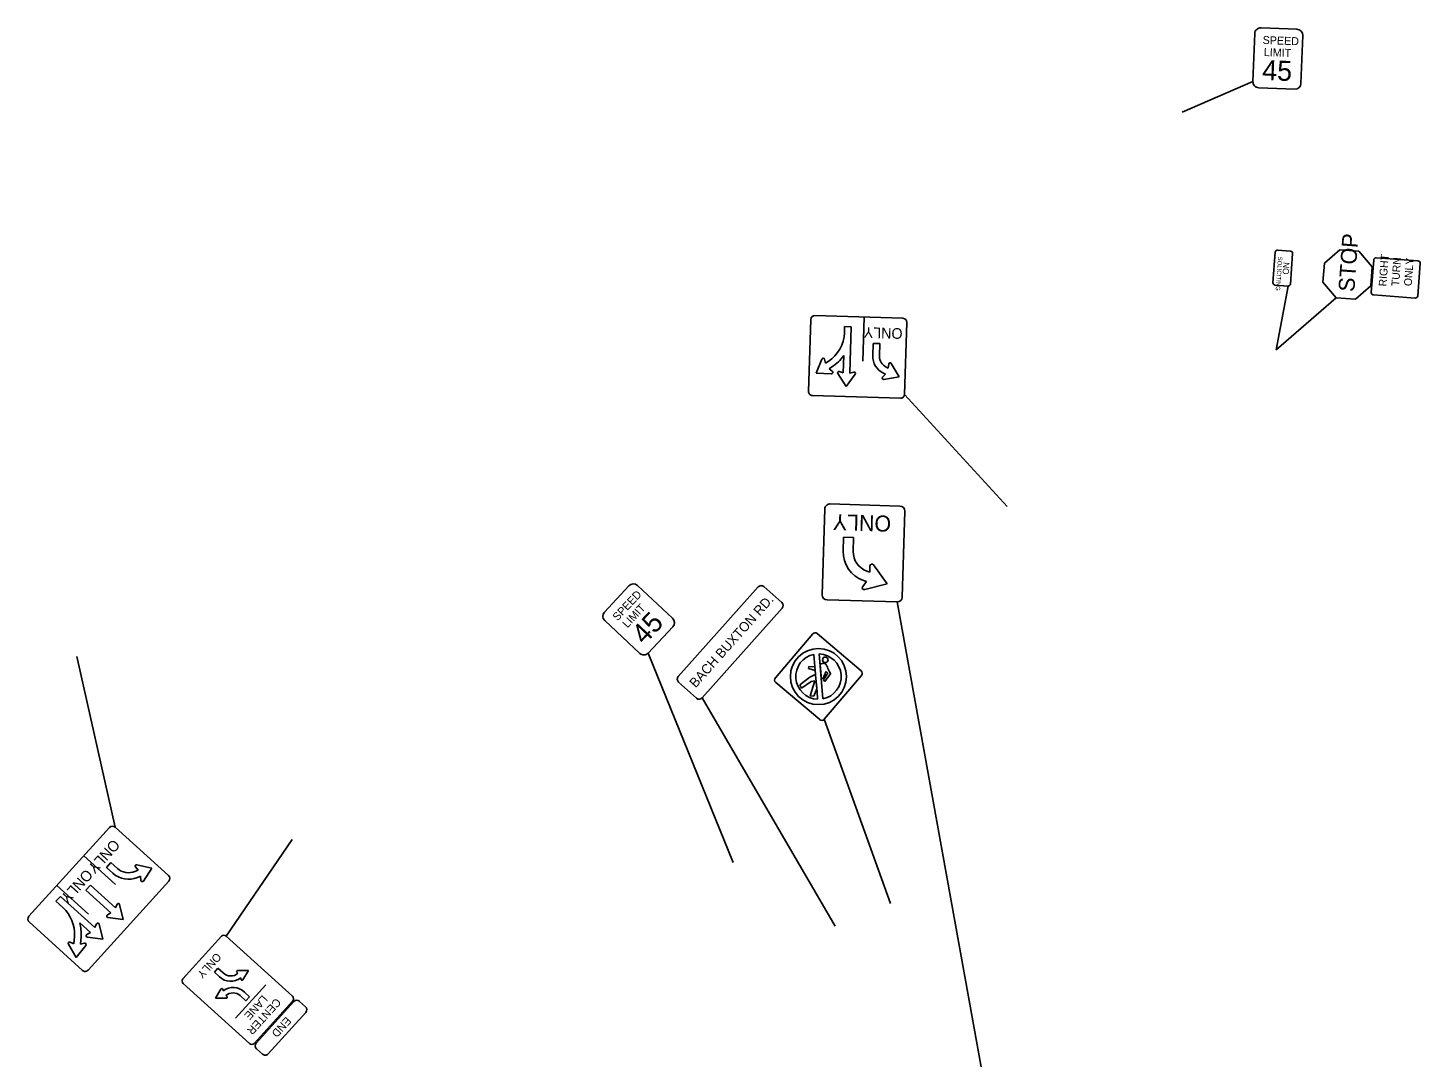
# Model space of a CAD drawing. Extents: x 1472333 to 1475205, y 385587 to 386650.
# Drawn here: x 1472332.8 to 1472767.9, y 386328.4 to 386650 of the extents above; entities that cross this region are included whole.
import ezdxf

# ---------------------------------------------------------------- set-up
doc = ezdxf.new("R2010")
doc.units = 0
doc.layers.add('RW_X_CL', color=7, linetype='Continuous')

msp = doc.modelspace()

# ---------------------------------------------------------------- linework, layer by layer
at = {"layer": 'RW_X_CL'}
for p, q in [((1472693.5, 386623.7), (1472715.61, 386633.24)), ((1472742.74, 386580.65), (1472737.92, 386576.5)), ((1472748.72, 386580.21), (1472742.74, 386580.65)), ((1472752.88, 386575.39), (1472748.72, 386580.21)), ((1472737.92, 386576.5), (1472737.48, 386570.51)), ((1472752.44, 386569.41), (1472752.88, 386575.39)), ((1472737.48, 386570.51), (1472741.63, 386565.69)), ((1472726.57, 386569.35), (1472722.88, 386549.43)), ((1472747.62, 386565.25), (1472752.44, 386569.41)), ((1472722.88, 386549.43), (1472741.63, 386565.69)), ((1472741.63, 386565.69), (1472747.62, 386565.25)), ((1472593.72, 386545.89), (1472594.16, 386559.63)), ((1472588.02, 386556.7), (1472587.96, 386554.72)), ((1472590.1, 386556.64), (1472588.02, 386556.7)), ((1472589.64, 386542.13), (1472590.1, 386556.64)), ((1472596.8, 386547.57), (1472596.92, 386551.42)), ((1472596.92, 386551.42), (1472599, 386551.35)), ((1472599, 386551.35), (1472598.88, 386547.5)), ((1472580.94, 386546.54), (1472579.08, 386542.08)), ((1472582.07, 386545.25), (1472581.73, 386546.49)), ((1472582.92, 386545.8), (1472582.07, 386545.25)), ((1472587.73, 386547.63), (1472587.56, 386542.19)), ((1472601.65, 386543.7), (1472601.83, 386544.98)), ((1472602.6, 386545.13), (1472605.03, 386540.95)), ((1472579.08, 386542.08), (1472583.92, 386541.94)), ((1472583.2, 386543.5), (1472584.05, 386544.05)), ((1472584.2, 386542.68), (1472583.2, 386543.5)), ((1472585.86, 386541.99), (1472588.47, 386537.93)), ((1472587.56, 386542.19), (1472586.35, 386542.61)), ((1472588.47, 386537.93), (1472591.33, 386541.82)), ((1472590.89, 386542.47), (1472589.64, 386542.13)), ((1472599.89, 386540.87), (1472600.76, 386541.82)), ((1472600.76, 386541.82), (1472600.14, 386542.11)), ((1472605.03, 386540.95), (1472600.26, 386540.17)), ((1472601.03, 386543.99), (1472601.65, 386543.7)), ((1472606.74, 386535.48), (1472638.78, 386500.44)), ((1472587.71, 386490.9), (1472587.58, 386486.53)), ((1472590.83, 386490.81), (1472587.71, 386490.9)), ((1472590.71, 386486.43), (1472590.83, 386490.81)), ((1472595.87, 386479.93), (1472594.93, 386480.26)), ((1472595.94, 386481.86), (1472595.87, 386479.93)), ((1472601.35, 386476.33), (1472597.07, 386482.21)), ((1472594.82, 386476.98), (1472593.66, 386475.44)), ((1472593.89, 386477.32), (1472594.82, 386476.98)), ((1472594.32, 386474.46), (1472601.35, 386476.33)), ((1472604.42, 386470.61), (1472631.01, 386323.53)), ((1472360.06, 386400.23), (1472348.09, 386453.59)), ((1472553.17, 386389.24), (1472526.64, 386454.64)), ((1472580.11, 386454.37), (1472581.25, 386440.33)), ((1472576.82, 386450.49), (1472576.75, 386449.78)), ((1472576.82, 386450.49), (1472576.75, 386449.78)), ((1472576.75, 386449.78), (1472578.84, 386449.21)), ((1472576.75, 386449.78), (1472578.84, 386449.21)), ((1472578.75, 386450.37), (1472576.82, 386450.49)), ((1472578.75, 386450.37), (1472576.82, 386450.49)), ((1472578.84, 386449.21), (1472578.82, 386449.44)), ((1472580.38, 386451.07), (1472580.39, 386450.92)), ((1472580.39, 386450.92), (1472580.76, 386446.38)), ((1472582.2, 386448.89), (1472582.74, 386448.4)), ((1472582.2, 386448.89), (1472582.74, 386448.4)), ((1472577.12, 386447.1), (1472574.05, 386444.76)), ((1472577.12, 386447.1), (1472574.05, 386444.76)), ((1472574.05, 386444.76), (1472574.5, 386443.71)), ((1472574.05, 386444.76), (1472574.5, 386443.71)), ((1472574.5, 386443.71), (1472577.58, 386445.72)), ((1472574.5, 386443.71), (1472577.58, 386445.72)), ((1472578.42, 386447.7), (1472577.12, 386447.1)), ((1472578.42, 386447.7), (1472577.12, 386447.1)), ((1472578.71, 386445.95), (1472577.29, 386441.23)), ((1472578.71, 386445.95), (1472577.29, 386441.23)), ((1472577.58, 386445.72), (1472578.71, 386445.95)), ((1472577.58, 386445.72), (1472578.71, 386445.95)), ((1472578.95, 386447.91), (1472578.42, 386447.7)), ((1472578.95, 386447.91), (1472578.42, 386447.7)), ((1472578.96, 386447.83), (1472578.95, 386447.91)), ((1472579.32, 386443.48), (1472578.96, 386447.83)), ((1472582.74, 386448.4), (1472581.38, 386446.23)), ((1472582.74, 386448.4), (1472581.38, 386446.23)), ((1472581.38, 386446.23), (1472581.83, 386445.77)), ((1472581.38, 386446.23), (1472581.83, 386445.77)), ((1472581.83, 386445.77), (1472583.59, 386448.2)), ((1472581.83, 386445.77), (1472583.59, 386448.2)), ((1472583.59, 386448.2), (1472583.58, 386448.21)), ((1472583.59, 386448.2), (1472583.58, 386448.21)), ((1472543.51, 386440.64), (1472585.05, 386369.32)), ((1472577.29, 386441.23), (1472578.4, 386441.17)), ((1472577.29, 386441.23), (1472578.4, 386441.17)), ((1472578.4, 386441.17), (1472579.32, 386443.48)), ((1472578.4, 386441.17), (1472579.32, 386443.48)), ((1472581.64, 386433.94), (1472602.31, 386376.36)), ((1472415.42, 386396.39), (1472394.75, 386366.21)), ((1472360.16, 386382.35), (1472350.29, 386391.31)), ((1472357.36, 386387.64), (1472358.76, 386389.18)), ((1472359.37, 386385.82), (1472357.36, 386387.64)), ((1472358.76, 386389.18), (1472360.77, 386387.36)), ((1472367.22, 386386.8), (1472366.4, 386387.79)), ((1472366.81, 386388.47), (1472371.53, 386387.44)), ((1472366.24, 386386.4), (1472367.22, 386386.8)), ((1472368.01, 386384.87), (1472367.04, 386384.47)), ((1472368.12, 386383.59), (1472368.01, 386384.87)), ((1472371.53, 386387.44), (1472368.89, 386383.4)), ((1472351.7, 386373.02), (1472341.82, 386381.97)), ((1472352.32, 386382.08), (1472350.92, 386380.54)), ((1472350.92, 386380.54), (1472358.75, 386373.44)), ((1472360.15, 386374.99), (1472352.32, 386382.08)), ((1472342.98, 386378.6), (1472341.58, 386377.06)), ((1472341.58, 386377.06), (1472343.74, 386375.1)), ((1472353.74, 386368.85), (1472342.98, 386378.6)), ((1472360.69, 386376.16), (1472360.15, 386374.99)), ((1472362.58, 386371.37), (1472361.47, 386376.08)), ((1472349, 386370.33), (1472352.34, 386367.31)), ((1472358.75, 386373.44), (1472357.64, 386372.79)), ((1472357.79, 386372.02), (1472362.58, 386371.37)), ((1472347.34, 386366.11), (1472347.17, 386363.82)), ((1472349.25, 386363.66), (1472349.42, 386365.95)), ((1472352.34, 386367.31), (1472351.23, 386366.65)), ((1472351.38, 386365.88), (1472356.17, 386365.23)), ((1472354.28, 386370.02), (1472353.74, 386368.85)), ((1472356.17, 386365.23), (1472355.06, 386369.94)), ((1472345.46, 386363.69), (1472347.9, 386359.52)), ((1472347.17, 386363.82), (1472345.97, 386364.29)), ((1472347.9, 386359.52), (1472350.92, 386363.29)), ((1472350.5, 386363.96), (1472349.25, 386363.66)), ((1472392.18, 386356.17), (1472391.06, 386354.93)), ((1472391.06, 386354.93), (1472392.65, 386353.49)), ((1472393.82, 386354.68), (1472392.18, 386356.17)), ((1472398.06, 386354.91), (1472398.42, 386354.58)), ((1472401.71, 386355.42), (1472398.35, 386355.4)), ((1472399.31, 386353.15), (1472399.44, 386352.54)), ((1472400.01, 386352.54), (1472401.71, 386355.42)), ((1472391.4, 386346.77), (1472393.09, 386349.63)), ((1472393.69, 386349.54), (1472393.83, 386349.06)), ((1472407.13, 386350.95), (1472397.72, 386340.57)), ((1472400.45, 386348.68), (1472402.06, 386347.22)), ((1472394.74, 386346.77), (1472391.4, 386346.77)), ((1472394.67, 386347.59), (1472395.03, 386347.26)), ((1472400.94, 386345.99), (1472399.18, 386347.58)), ((1472402.06, 386347.22), (1472400.94, 386345.99))]:
    msp.add_line(p, q, dxfattribs=at)
for points in [[(1472729.38, 386649.6), (1472718.13, 386650.03)], [(1472716.19, 386648.23), (1472715.61, 386633.24)], [(1472730.6, 386632.67), (1472731.18, 386647.66)], [(1472717.41, 386631.3), (1472728.66, 386630.86)], [(1472722.54, 386579.93), (1472721.85, 386570.38)], [(1472727.36, 386580.26), (1472723.27, 386580.56)], [(1472727.31, 386569.98), (1472728, 386579.53)], [(1472752.6, 386567.34), (1472753.35, 386577.5)], [(1472754.13, 386578.17), (1472767.19, 386577.21)], [(1472767.86, 386576.43), (1472767.11, 386566.27)], [(1472722.48, 386569.65), (1472726.57, 386569.35)], [(1472766.33, 386565.6), (1472753.27, 386566.56)], [(1472577.46, 386558.91), (1472576.75, 386536.42)], [(1472606.23, 386559.26), (1472578.75, 386560.12)], [(1472606.74, 386535.48), (1472607.44, 386557.97)], [(1472577.96, 386535.13), (1472605.45, 386534.27)], [(1472605.29, 386500.6), (1472583.43, 386501.24)], [(1472581.82, 386499.72), (1472581.04, 386472.86)], [(1472606.03, 386472.13), (1472606.81, 386498.99)], [(1472520.63, 386475.66), (1472512.95, 386467.45)], [(1472534.24, 386465.5), (1472523.28, 386475.75)], [(1472560.99, 386475.29), (1472536.05, 386447.29)], [(1472562.76, 386475.4), (1472568.36, 386470.41)], [(1472582.55, 386471.25), (1472604.42, 386470.61)], [(1472543.51, 386440.64), (1472568.46, 386468.64)], [(1472513.04, 386464.8), (1472523.99, 386454.55)], [(1472526.64, 386454.64), (1472534.33, 386462.85)], [(1472578.04, 386460.61), (1472566.39, 386446.88)], [(1472593.17, 386449.08), (1472579.45, 386460.72)], [(1472578.43, 386454.23), (1472578.74, 386450.42), (1472578.83, 386449.44), (1472578.82, 386449.44)], [(1472578.82, 386449.44), (1472578.75, 386450.37), (1472578.75, 386450.37)], [(1472578.82, 386449.44), (1472578.96, 386447.83), (1472579.39, 386442.6), (1472579.59, 386440.2)], [(1472580.39, 386450.92), (1472580.39, 386450.92)], [(1472536.15, 386445.53), (1472541.75, 386440.54)], [(1472566.5, 386445.47), (1472580.23, 386433.83)], [(1472581.64, 386433.94), (1472593.28, 386447.67)], [(1472358.3, 386400.15), (1472333.11, 386372.37)], [(1472376.73, 386385.12), (1472360.06, 386400.23)], [(1472351.63, 386355.57), (1472376.82, 386383.35)], [(1472333.2, 386370.6), (1472349.86, 386355.49)], [(1472393.34, 386366.14), (1472381.25, 386352.8)], [(1472415.5, 386347.4), (1472394.75, 386366.21)], [(1472381.32, 386351.39), (1472402.06, 386332.58)], [(1472403.47, 386332.65), (1472415.57, 386345.99)], [(1472404.17, 386332.75), (1472415.92, 386345.72)], [(1472417.69, 386345.8), (1472419.54, 386344.12)], [(1472419.63, 386342.36), (1472407.87, 386329.39)], [(1472406.11, 386329.31), (1472404.25, 386330.99)]]:
    msp.add_lwpolyline(points, dxfattribs=at)
for centre, radius in [((1472579.84, 386447.29), 8.77), ((1472581.97, 386452.53), 0.864)]:
    msp.add_circle(centre, radius, dxfattribs=at)
for centre, radius, start, end in [((1472718.06, 386648.16), 1.88, 87.8, 177.8), ((1472729.3, 386647.73), 1.88, 357.8, 87.8), ((1472717.49, 386633.17), 1.88, 177.8, 267.8), ((1472728.73, 386632.74), 1.88, 267.8, 357.8), ((1472723.22, 386579.88), 0.684, 85.859, 175.859), ((1472727.31, 386579.58), 0.684, 355.859, 85.859), ((1472754.08, 386577.45), 0.727, 85.7879, 175.7879), ((1472767.13, 386576.49), 0.727, 355.7879, 85.7879), ((1472722.53, 386570.33), 0.684, 175.859, 265.859), ((1472726.62, 386570.03), 0.684, 265.859, 355.859), ((1472753.33, 386567.29), 0.727, 175.7879, 265.7879), ((1472766.39, 386566.33), 0.727, 265.7879, 355.7879), ((1472578.71, 386558.87), 1.25, 88.2, 178.2), ((1472606.19, 386558.01), 1.25, 358.2, 88.2), ((1472576.92, 386555.07), 11.04, 302.9021, 358.2), ((1472581.33, 386546.38), 0.417, 15.5403, 157.4184), ((1472576.92, 386555.07), 13.13, 302.9021, 325.4745), ((1472602.63, 386547.38), 5.83, 178.2, 244.734), ((1472602.63, 386547.38), 3.75, 178.2, 244.734), ((1472602.24, 386544.92), 0.417, 30.2177, 172.0958), ((1472583.93, 386542.36), 0.417, 268.3858, 50.2639), ((1472586.21, 386542.22), 0.417, 70.8382, 212.7163), ((1472591, 386542.07), 0.417, 323.6837, 105.5618), ((1472600.19, 386540.58), 0.417, 137.3722, 279.2503), ((1472578, 386536.38), 1.25, 178.2, 268.2), ((1472605.49, 386535.52), 1.25, 268.2, 358.2), ((1472583.38, 386499.67), 1.56, 88.3321, 178.3321), ((1472605.25, 386499.04), 1.56, 358.3321, 88.3321), ((1472597.06, 386486.25), 9.48, 178.3321, 250.4746), ((1472597.06, 386486.25), 6.35, 178.3321, 250.4708), ((1472596.56, 386481.84), 0.625, 36.0864, 177.8581), ((1472522, 386474.38), 1.88, 46.9115, 136.9115), ((1472561.93, 386474.46), 1.25, 48.3, 138.3), ((1472594.16, 386475.06), 0.625, 143.1257, 284.8974), ((1472567.53, 386469.47), 1.25, 318.3, 48.3), ((1472582.6, 386472.81), 1.56, 178.3321, 268.3321), ((1472604.46, 386472.17), 1.56, 268.3321, 358.3321), ((1472514.32, 386466.17), 1.87, 136.9115, 226.9115), ((1472532.96, 386464.14), 1.88, 316.9115, 46.9115), ((1472578.8, 386459.96), 1, 49.6773, 139.6773), ((1472525.27, 386455.92), 1.87, 226.9115, 316.9115), ((1472579.84, 386447.29), 7.09, 101.5252, 267.9252), ((1472579.84, 386447.29), 7.09, 101.5252, 267.9252), ((1472579.84, 386447.29), 7.09, 281.4963, 87.8486), ((1472592.52, 386448.31), 1, 319.6773, 49.6773), ((1472536.98, 386446.46), 1.25, 138.3, 228.3), ((1472567.15, 386446.24), 1, 139.6773, 229.6773), ((1472542.58, 386441.47), 1.25, 228.3, 318.3), ((1472580.87, 386434.59), 1, 229.6773, 319.6773), ((1472359.22, 386399.31), 1.25, 47.8, 137.8), ((1472366.72, 386388.06), 0.417, 77.801, 219.6791), ((1472364.27, 386391.22), 7.29, 227.8, 292.3173), ((1472364.27, 386391.22), 5.21, 227.8, 292.3173), ((1472368.54, 386383.63), 0.417, 184.9555, 326.8336), ((1472375.89, 386384.19), 1.25, 317.8, 47.8), ((1472336.33, 386366.92), 11.04, 355.7857, 47.8), ((1472361.07, 386375.98), 0.417, 13.2837, 155.1618), ((1472334.04, 386371.53), 1.25, 137.8, 227.8), ((1472336.33, 386366.92), 13.12, 355.7857, 15.0745), ((1472354.66, 386369.84), 0.417, 13.2837, 155.1618), ((1472357.85, 386372.43), 0.417, 120.4382, 262.3163), ((1472351.44, 386366.29), 0.417, 120.4382, 262.3163), ((1472394.08, 386365.47), 1, 47.8, 137.8), ((1472345.82, 386363.9), 0.417, 68.4239, 210.302), ((1472350.6, 386363.55), 0.417, 321.2694, 103.1475), ((1472350.7, 386356.41), 1.25, 227.8, 317.8), ((1472381.99, 386352.13), 1, 137.8, 227.8), ((1472396.18, 386357.12), 5.07, 225.8828, 308.2422), ((1472396.18, 386357.12), 3.4, 225.9889, 311.4204), ((1472398.35, 386355.07), 0.334, 89.9541, 209.8), ((1472393.37, 386349.45), 0.334, 15.76, 147.7961), ((1472396.92, 386345.05), 5.07, 45.8828, 127.6482), ((1472396.92, 386345.05), 3.4, 48.2572, 131.5022), ((1472399.73, 386352.72), 0.334, 213.4089, 327.7961), ((1472394.74, 386347.1), 0.334, 269.9541, 29.8), ((1472414.82, 386346.66), 1, 317.8, 47.8), ((1472416.85, 386344.88), 1.25, 47.8, 137.8), ((1472418.7, 386343.2), 1.25, 317.8, 47.8), ((1472402.73, 386333.32), 1, 227.8, 317.8), ((1472405.09, 386331.91), 1.25, 137.8, 227.8), ((1472406.95, 386330.23), 1.25, 227.8, 317.8)]:
    msp.add_arc(centre, radius, start, end, dxfattribs=at)
for points in [[(1472583.58, 386448.21), (1472583.16, 386449.08), (1472582.51, 386450.46), (1472582.27, 386450.97), (1472582.17, 386451.1), (1472582.04, 386451.21), (1472581.73, 386451.47), (1472581.04, 386451.44), (1472580.63, 386451.2), (1472580.38, 386451.07)], [(1472583.58, 386448.21), (1472583.16, 386449.08), (1472582.51, 386450.46), (1472582.27, 386450.97), (1472582.17, 386451.1), (1472582.04, 386451.21), (1472581.73, 386451.47), (1472581.04, 386451.44), (1472580.63, 386451.2), (1472580.38, 386451.07)], [(1472580.76, 386446.38), (1472580.83, 386446.41), (1472581.02, 386446.53), (1472581.29, 386446.9), (1472581.49, 386447.27), (1472581.81, 386447.95), (1472582.02, 386448.43), (1472582.2, 386448.89)], [(1472580.76, 386446.38), (1472580.83, 386446.41), (1472581.02, 386446.53), (1472581.29, 386446.9), (1472581.49, 386447.27), (1472581.81, 386447.95), (1472582.02, 386448.43), (1472582.2, 386448.89)]]:
    msp.add_open_spline(points, degree=3, dxfattribs=at)

# ---------------------------------------------------------------- texts
for s, height, rotation, p in [('SPEED', 2.5, 357.8, (1472718.6, 386645.01)), ('45', 6.25, 357.8, (1472718.43, 386633.76)), ('LIMIT', 2.5, 357.8, (1472718.97, 386641.24)), ('STOP', 5, 85.7879, (1472747.28, 386567.41)), ('RIGHT', 2.424, 85.7879, (1472757.31, 386569.16)), ('SOLICITING', 1.368, 265.859, (1472723.47, 386578.58)), ('NO', 1.915, 265.859, (1472725.13, 386576.85)), ('TURN', 2.424, 85.7879, (1472761.26, 386569.25)), ('ONLY', 2.424, 85.7879, (1472765.2, 386569.26)), ('ONLY', 3.333, 178.2, (1472606.17, 386556.13)), ('ONLY', 5, 178.3321, (1472602.61, 386497.55)), ('SPEED', 2.5, 46.9115, (1472517.05, 386464.51)), ('LIMIT', 2.5, 46.9115, (1472520.14, 386462.33)), ('       BACH BUXTON RD.', 3, 48.3, (1472536.27, 386437.77)), ('45', 6.25, 46.9115, (1472525.45, 386457.02)), ('ONLY', 3.333, 227.8, (1472359.39, 386396.7)), ('ONLY', 3.333, 227.8, (1472350.93, 386387.36)), ('ONLY', 2.5, 227.8, (1472391.64, 386361.16)), ('LANE', 2.5, 227.8, (1472406.1, 386347.95)), ('CENTER', 2.5, 227.8, (1472410.29, 386346.99)), ('END', 2.5, 227.8, (1472413.5, 386341.18))]:
    msp.add_text(s, height=height, rotation=rotation, dxfattribs=at).set_placement(p)

doc.saveas('drawing.dxf')
